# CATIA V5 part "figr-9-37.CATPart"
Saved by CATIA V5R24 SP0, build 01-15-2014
Part number: Part1
Bounding box of the stored display mesh (mm): x 0 to 200, y -70 to 70, z -70 to 70
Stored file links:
  D:\KAVITA\CATIA V5-6R2014 Project_ Kavita\CATIA V5-6R2014_partfiles\Partfiles\c09_catia_v5-6r2014_prt\figr-9-37.CATPart
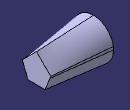
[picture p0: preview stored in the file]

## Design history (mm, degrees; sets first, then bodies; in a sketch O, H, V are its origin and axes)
Set1
  Plane1: type Offset, RefPlane yz-plane, Offset 200
Body1 (main body)
  Sketch1 on yz-plane, origin (0, 0, 0), H (0, 1, 0), V (0, 0, 1)
    circle A1 centre (0, 0) radius 70
    point P1 (70, 0)
    point P2 (-48.9898, -50)
    point P3 (48.9898, -50)
    point P4 (69.282, 10)
    point P5 (-69.282, 10)
    point P6 (0, 70)
    radius A1 = 70
    coincidence: A1 P1, P1 H, P2 A1, P3 A1, P4 A1, P5 A1, P6 V
  Sketch2 on Plane1, origin (200, 0, 0), H (0, 1, 0), V (0, 0, 1)
    point P1 (-30, -40)
    line L1 (-30, -40) -> (30, -40)
    point P2 (30, -40)
    line L2 (30, -40) -> (50, 10)
    point P3 (50, 10)
    line L3 (50, 10) -> (0, 60)
    point P4 (0, 60)
    line L4 (0, 60) -> (-50, 10)
    point P5 (-50, 10)
    line L5 (-50, 10) -> (-30, -40)
    horizontal: L1 H
    coincidence: P4 V
    symmetry: P3 P5 V, P2 P1 V
  Loft1: Sections (edge of Sketch1; Sketch2), SectionCouplingPoints ({coupling CouplingPoints (vertex of Sketch1; vertex [element of Sketch2 | element of Sketch2])}; {coupling CouplingPoints (vertex of Sketch1; vertex [element of Sketch2 | element of Sketch2])}; {coupling CouplingPoints (vertex of Sketch1; vertex [element of Sketch2 | element of Sketch2])}; {coupling CouplingPoints (vertex of Sketch1; vertex [element of Sketch2 | element of Sketch2])})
